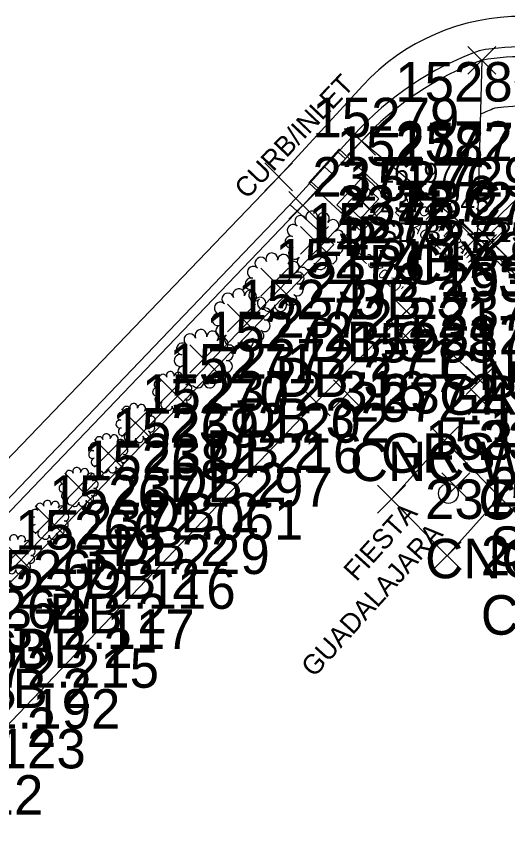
# Model space of a CAD drawing. Extents: x 2377639 to 2379738, y 729875 to 732734.
# Drawn here: x 2378591.47 to 2378616.34, y 730741.64 to 730783.14 of the extents above; entities that cross this region are included whole.
import ezdxf

# ---------------------------------------------------------------- set-up
doc = ezdxf.new("R2010")
doc.units = 0
for name, color, linetype in [('Default', 7, 'Continuous'), ('TOPO_CURBGTR_Back-of-Curb', 7, 'Continuous'), ('TOPO_CURBGTR_Face-of-Curb', 7, 'Continuous'), ('TOPO_CURBGTR_Lip-of-Gutter', 7, 'Continuous'), ('TOPO_DATA_Elevations', 7, 'Continuous'), ('TOPO_DATA_Notes', 7, 'Continuous'), ('TOPO_LNDSCP_Tree', 7, 'Continuous'), ('TOPO_SIGNS_Post-Single', 7, 'Continuous'), ('TOPO_STORM_Inlet', 7, 'Continuous'), ('TOPO_STORM_Line-Other', 7, 'Continuous'), ('TOPO_STRUCT_Conc-Box-Culv', 7, 'Continuous'), ('TOPO_STRUCT_Concrete-Wall', 7, 'Continuous'), ('TOPO_SW_Back', 7, 'Continuous')]:
    doc.layers.add(name, color=color, linetype=linetype)

# ---------------------------------------------------------------- blocks, each defined once
blk = doc.blocks.new('DB_1')
at = {"layer": 'Default'}
for centre, radius, start, end in [((-0.0592, 0.0812), 0.0254, 16.7823, 235.0388), ((-0.0121, 0.0998), 0.0254, 347.9823, 206.2388), ((0.0381, 0.0934), 0.0254, 319.1823, 177.4388), ((0.079, 0.0636), 0.0254, 290.3823, 148.6388), ((-0.0916, 0.0423), 0.0254, 45.5823, 263.8388), ((0.1005, 0.0177), 0.0254, 261.5823, 119.8388), ((-0.1011, -0.0074), 0.0254, 74.3823, 292.6388), ((0, 0), 0.00318, 0, 180), ((0, 0), 0.00318, 180, 0), ((-0.0856, -0.0556), 0.0254, 103.1823, 321.4388), ((0.0972, -0.0328), 0.0254, 232.7823, 91.0388), ((0.07, -0.0755), 0.0254, 203.9823, 62.2388), ((-0.0487, -0.0903), 0.0254, 131.9823, 278.4601), ((-0.025, -0.0997), 0.0254, 218.161, 4.6388), ((0.0256, -0.0998), 0.0254, 175.1823, 33.4388)]:
    blk.add_arc(centre, radius, start, end, dxfattribs=at)

msp = doc.modelspace()

# ---------------------------------------------------------------- linework, layer by layer
at = {"layer": 'TOPO_CURBGTR_Back-of-Curb'}
msp.add_lwpolyline([(2378428.642, 730588.821), (2378465.502, 730627.295), (2378502.362, 730665.573), (2378505.999, 730669.314), (2378527.479, 730691.628), (2378605.975, 730773.579), (2378608.942, 730776.83)], dxfattribs=at)
for centre, radius, start, end in [((2378616.993, 730770.176), 10.918, 48.5009, 100.3444), ((2378620.336, 730766.431), 15.426, 110.1073, 137.6151)]:
    msp.add_arc(centre, radius, start, end, dxfattribs=at)
at = {"layer": 'TOPO_CURBGTR_Face-of-Curb'}
msp.add_lwpolyline([(2378428.284, 730589.169), (2378465.141, 730627.641), (2378502.003, 730665.921), (2378505.64, 730669.662), (2378527.118, 730691.974), (2378605.61, 730773.921), (2378608.573, 730777.167)], dxfattribs=at)
for centre, radius, start, end in [((2378620.336, 730766.431), 15.926, 109.9542, 137.6151), ((2378616.993, 730770.176), 11.418, 48.3859, 100.5593)]:
    msp.add_arc(centre, radius, start, end, dxfattribs=at)
at = {"layer": 'TOPO_CURBGTR_Lip-of-Gutter'}
msp.add_lwpolyline([(2378609.002, 730779.641), (2378604.75, 730775.021), (2378431.05, 730594.21), (2378426.074, 730588.908)], dxfattribs=at)
msp.add_arc((2378617.021, 730772.2), 10.939, 89.5067, 137.1387, dxfattribs=at)
at = {"layer": 'TOPO_DATA_Elevations'}
for p, q in [((2378614.326, 730780.21), (2378615.74, 730781.624)), ((2378614.326, 730781.624), (2378615.74, 730780.21)), ((2378608.235, 730776.123), (2378609.649, 730777.537)), ((2378608.235, 730777.537), (2378609.649, 730776.123)), ((2378604.043, 730774.314), (2378605.457, 730775.728)), ((2378604.043, 730775.728), (2378605.457, 730774.314)), ((2378608.288, 730773.05), (2378609.702, 730774.464)), ((2378608.288, 730774.464), (2378609.702, 730773.05)), ((2378605.268, 730772.872), (2378606.682, 730774.286)), ((2378605.268, 730774.286), (2378606.682, 730772.872)), ((2378608.643, 730773.371), (2378609.351, 730774.079)), ((2378608.643, 730774.079), (2378609.351, 730773.371)), ((2378608.643, 730773.371), (2378609.351, 730774.079)), ((2378608.643, 730774.079), (2378609.351, 730773.371)), ((2378614.084, 730771.271), (2378615.498, 730772.685)), ((2378614.084, 730772.685), (2378615.498, 730771.271)), ((2378605.857, 730771.101), (2378607.271, 730772.515)), ((2378605.857, 730772.515), (2378607.271, 730771.101)), ((2378613.978, 730771.162), (2378615.392, 730772.576)), ((2378613.978, 730772.576), (2378615.392, 730771.162)), ((2378614.854, 730771.013), (2378616.268, 730772.427)), ((2378614.854, 730772.427), (2378616.268, 730771.013)), ((2378614.363, 730770.694), (2378615.777, 730772.108)), ((2378614.363, 730772.108), (2378615.777, 730770.694)), ((2378603.84, 730768.985), (2378605.254, 730770.399)), ((2378603.84, 730770.399), (2378605.254, 730768.985)), ((2378602.165, 730767.171), (2378603.579, 730768.585)), ((2378602.165, 730768.585), (2378603.579, 730767.171)), ((2378610.518, 730767.526), (2378611.932, 730768.94)), ((2378610.518, 730768.94), (2378611.932, 730767.526)), ((2378610.46, 730766.273), (2378611.874, 730767.687)), ((2378610.46, 730767.687), (2378611.874, 730766.273)), ((2378600.249, 730765.11), (2378601.663, 730766.524)), ((2378600.249, 730766.524), (2378601.663, 730765.11)), ((2378614.241, 730764.01), (2378615.655, 730765.424)), ((2378614.241, 730765.424), (2378615.655, 730764.01)), ((2378598.653, 730763.485), (2378600.067, 730764.899)), ((2378598.653, 730764.899), (2378600.067, 730763.485)), ((2378607.518, 730763.34), (2378608.932, 730764.754)), ((2378607.518, 730764.754), (2378608.932, 730763.34)), ((2378614.351, 730762.976), (2378615.765, 730764.39)), ((2378614.351, 730764.39), (2378615.765, 730762.976)), ((2378605.944, 730762.921), (2378607.358, 730764.335)), ((2378605.944, 730764.335), (2378607.358, 730762.921)), ((2378596.8, 730761.86), (2378598.214, 730763.274)), ((2378596.8, 730763.274), (2378598.214, 730761.86)), ((2378612.44, 730760.979), (2378613.854, 730762.393)), ((2378612.44, 730762.393), (2378613.854, 730760.979)), ((2378595.419, 730760.323), (2378596.833, 730761.737)), ((2378595.419, 730761.737), (2378596.833, 730760.323)), ((2378593.917, 730758.618), (2378595.331, 730760.032)), ((2378593.917, 730760.032), (2378595.331, 730758.618)), ((2378613.008, 730758.626), (2378614.422, 730760.04)), ((2378613.008, 730760.04), (2378614.422, 730758.626)), ((2378609.747, 730758.002), (2378611.161, 730759.416)), ((2378609.747, 730759.416), (2378611.161, 730758.002)), ((2378615.231, 730758.101), (2378616.645, 730759.515)), ((2378615.231, 730759.515), (2378616.645, 730758.101)), ((2378592.428, 730756.959), (2378593.842, 730758.373)), ((2378592.428, 730758.373), (2378593.842, 730756.959)), ((2378590.729, 730755.219), (2378592.143, 730756.633)), ((2378590.729, 730756.633), (2378592.143, 730755.219)), ((2378612.569, 730755.146), (2378613.983, 730756.56)), ((2378612.569, 730756.56), (2378613.983, 730755.146))]:
    msp.add_line(p, q, dxfattribs=at)
at = {"layer": 'TOPO_SIGNS_Post-Single'}
msp.add_circle((2378613.342, 730759), 0.5, dxfattribs=at)
at = {"layer": 'TOPO_STORM_Inlet'}
for p, q in [((2378607.76, 730776.277), (2378608.129, 730775.94)), ((2378607.074, 730775.525), (2378607.444, 730775.188)), ((2378606.389, 730774.774), (2378606.758, 730774.437))]:
    msp.add_line(p, q, dxfattribs=at)
at = {"layer": 'TOPO_STORM_Line-Other'}
for q in [(2378186.996, 730332.08), (2378188.378, 730333.526)]:
    msp.add_line((2378608.313, 730773.027), q, dxfattribs=at)
at = {"layer": 'TOPO_STRUCT_Conc-Box-Culv'}
for p, q in [((2378609.087, 730774.596), (2378608.164, 730773.611)), ((2378609.826, 730773.903), (2378609.087, 730774.596)), ((2378608.164, 730773.611), (2378608.903, 730772.918)), ((2378608.903, 730772.918), (2378609.826, 730773.903))]:
    msp.add_line(p, q, dxfattribs=at)
for points in [[(2378608.951, 730772.242), (2378610.507, 730773.901), (2378607.812, 730776.428), (2378606.269, 730774.723), (2378608.951, 730772.242)], [(2378608.936, 730772.443), (2378607.688, 730773.613), (2378609.054, 730775.071), (2378610.302, 730773.901)]]:
    msp.add_lwpolyline(points, close=True, dxfattribs=at)
at = {"layer": 'TOPO_STRUCT_Concrete-Wall'}
for p, q in [((2378608.942, 730776.83), (2378608.573, 730777.167)), ((2378605.699, 730773.276), (2378605.322, 730773.62))]:
    msp.add_line(p, q, dxfattribs=at)
for points in [[(2378625.619, 730776.878), (2378622.895, 730773.793), (2378617.227, 730774.318), (2378614.791, 730771.978), (2378621.659, 730765.194)], [(2378625.848, 730776.635), (2378623.033, 730773.446), (2378617.348, 730773.972), (2378615.268, 730771.975), (2378621.893, 730765.431)]]:
    msp.add_lwpolyline(points, dxfattribs=at)
at = {"layer": 'TOPO_SW_Back'}
for points in [[(2378615.033, 730780.917), (2378614.791, 730771.978), (2378608.942, 730776.83)], [(2378532.376, 730696.741), (2378534.182, 730695.012), (2378607.539, 730771.597), (2378605.699, 730773.276)], [(2378658.449, 730745.047), (2378650.577, 730736.964), (2378643.234, 730744.058), (2378632.385, 730754.515), (2378614.685, 730771.869), (2378614.791, 730771.978)], [(2378474.976, 730627.551), (2378508.088, 730660.214), (2378532.765, 730686.324), (2378606.651, 730763.628), (2378611.225, 730768.233), (2378618.352, 730761.502)], [(2378613.147, 730761.686), (2378610.454, 730758.709), (2378613.276, 730755.853), (2378615.938, 730758.808), (2378613.147, 730761.686)]]:
    msp.add_lwpolyline(points, dxfattribs=at)
for centre, radius, start, end in [((2378620.336, 730766.431), 12.926, 111.0744, 114.5817), ((2378616.993, 730770.176), 8.418, 49.2218, 98.92)]:
    msp.add_arc(centre, radius, start, end, dxfattribs=at)

# ---------------------------------------------------------------- block references
at = {"layer": 'TOPO_LNDSCP_Tree'}
for p, xscale, yscale in [((2378606.564, 730771.808), 11.811, 11.811), ((2378604.547, 730769.692), 11.811, 11.811), ((2378602.872, 730767.878), 11.811, 11.811), ((2378600.956, 730765.817), 11.811, 11.811), ((2378599.36, 730764.192), 7.8740000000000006, 7.8740000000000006), ((2378597.507, 730762.567), 7.8740000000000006, 7.8740000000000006), ((2378596.126, 730761.03), 7.8740000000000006, 7.8740000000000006), ((2378594.624, 730759.325), 7.8740000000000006, 7.8740000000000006), ((2378593.135, 730757.666), 7.8740000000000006, 7.8740000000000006), ((2378591.436, 730755.926), 7.8740000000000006, 7.8740000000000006)]:
    msp.add_blockref('DB_1', p, dxfattribs=dict(at, xscale=xscale, yscale=yscale))

# ---------------------------------------------------------------- texts
at = {"layer": 'TOPO_DATA_Elevations'}
for s, height, p in [('15280', 2, (2378610.649, 730778.83)), ('15279', 2, (2378606.457, 730777.021)), ('2372.287', 2, (2378610.649, 730775.83)), ('15277', 2, (2378610.702, 730775.757)), ('15278', 2, (2378607.682, 730775.579)), ('2371.729', 2, (2378606.457, 730774.021)), ('15276', 2, (2378608.271, 730773.808)), ('16197', 1, (2378609.851, 730774.725)), ('16197', 1, (2378609.851, 730774.725)), ('TBC CUT', 2, (2378610.649, 730772.83)), ('2372.314', 2, (2378610.702, 730772.757)), ('2372.275', 2, (2378607.682, 730772.579)), ('2372.345', 1, (2378609.851, 730773.225)), ('2372.345', 1, (2378609.851, 730773.225)), ('15275', 2, (2378606.254, 730771.692)), ('LIP', 2, (2378606.457, 730771.021)), ('2372.287', 2, (2378608.271, 730770.808)), ('SD BX -2.25INV 12RCP SW', 1, (2378609.851, 730771.725)), ('SD BX -2.25INV 12RCP SW', 1, (2378609.851, 730771.725)), ('15289', 2, (2378612.932, 730770.233)), ('15274', 2, (2378604.579, 730769.878)), ('TBC', 2, (2378607.682, 730769.579)), ('JBX', 2, (2378610.702, 730769.757)), ('2372.293', 2, (2378606.254, 730768.692)), ('15313', 2, (2378612.874, 730768.98)), ('15273', 2, (2378602.663, 730767.817)), ('DB 3', 2, (2378608.271, 730767.808)), ('2372.547', 2, (2378612.932, 730767.233)), ('2372.221', 2, (2378604.579, 730766.878)), ('15272', 2, (2378601.067, 730766.192)), ('DB 3', 2, (2378606.254, 730765.692)), ('15312', 2, (2378609.932, 730766.047)), ('2372.130', 2, (2378612.874, 730765.98)), ('15288', 2, (2378608.358, 730765.628)), ('15271', 2, (2378599.214, 730764.567)), ('2372.271', 2, (2378602.663, 730764.817)), ('CNC WLK AP', 2, (2378612.932, 730764.233)), ('DB 3', 2, (2378604.579, 730763.878)), ('15308', 2, (2378614.854, 730763.686)), ('2372.316', 2, (2378601.067, 730763.192)), ('15270', 2, (2378597.833, 730763.03)), ('2372.328', 2, (2378609.932, 730763.047)), ('GRS', 2, (2378612.874, 730762.98)), ('2372.417', 2, (2378608.358, 730762.628)), ('2372.202', 2, (2378599.214, 730761.567)), ('DB 3', 2, (2378602.663, 730761.817)), ('15269', 2, (2378596.331, 730761.325)), ('15307', 2, (2378615.422, 730761.333)), ('15311', 2, (2378612.161, 730760.709)), ('2372.508', 2, (2378614.854, 730760.686)), ('2372.216', 2, (2378597.833, 730760.03)), ('DB 2', 2, (2378601.067, 730760.192)), ('GRS', 2, (2378609.932, 730760.047)), ('15268', 2, (2378594.842, 730759.666)), ('CNC WLK', 2, (2378608.358, 730759.628)), ('2372.297', 2, (2378596.331, 730758.325)), ('DB 2', 2, (2378599.214, 730758.567)), ('2372.368', 2, (2378615.422, 730758.333)), ('15267', 2, (2378593.143, 730757.926)), ('15310', 2, (2378614.983, 730757.853)), ('2372.540', 2, (2378612.161, 730757.709)), ('CNC PAD AP', 2, (2378614.854, 730757.686)), ('DB 2', 2, (2378597.833, 730757.03)), ('2372.061', 2, (2378594.842, 730756.666)), ('15266', 2, (2378591.417, 730756.164)), ('DB 2', 2, (2378596.331, 730755.325)), ('SGN FIESTA MXICN RSTRNT', 2, (2378615.422, 730755.333)), ('2372.229', 2, (2378593.143, 730754.926)), ('CNC PAD AP', 2, (2378612.161, 730754.709)), ('2372.673', 2, (2378614.983, 730754.853)), ('15265', 2, (2378589.343, 730754.137)), ('DB 2', 2, (2378594.842, 730753.666)), ('2372.116', 2, (2378591.417, 730753.164)), ('15264', 2, (2378587.539, 730752.17)), ('DB 2', 2, (2378593.143, 730751.926)), ('CNC PAD AP', 2, (2378614.983, 730751.853)), ('2372.117', 2, (2378589.343, 730751.137)), ('15263', 2, (2378585.58, 730750.1)), ('DB 2', 2, (2378591.417, 730750.164)), ('2372.215', 2, (2378587.539, 730749.17)), ('DB 2', 2, (2378589.343, 730748.137)), ('2372.192', 2, (2378585.58, 730747.1)), ('DB 2', 2, (2378587.539, 730746.17)), ('2372.123', 2, (2378583.83, 730745.089)), ('2372.212', 2, (2378581.681, 730742.746))]:
    msp.add_text(s, height=height, dxfattribs=at).set_placement(p)
at = {"layer": 'TOPO_DATA_Notes'}
for s, height, rotation, p in [('CURB/INLET', 1, 46.4356, (2378603.143, 730773.849)), ('STORM DRAIN ', 0.5, 316.6468, (2378611.149, 730773.856)), ('LID ACCESS', 0.5, 316.6468, (2378610.577, 730773.25)), ("INV=2370.10'", 0.5, 315.8607, (2378607.858, 730771.886)), ('FIESTA', 1, 47.8084, (2378608.688, 730754.506)), (' GUADALAJARA', 1, 47.8084, (2378606.29, 730749.379))]:
    msp.add_text(s, height=height, rotation=rotation, dxfattribs=at).set_placement(p)

doc.saveas('drawing.dxf')
